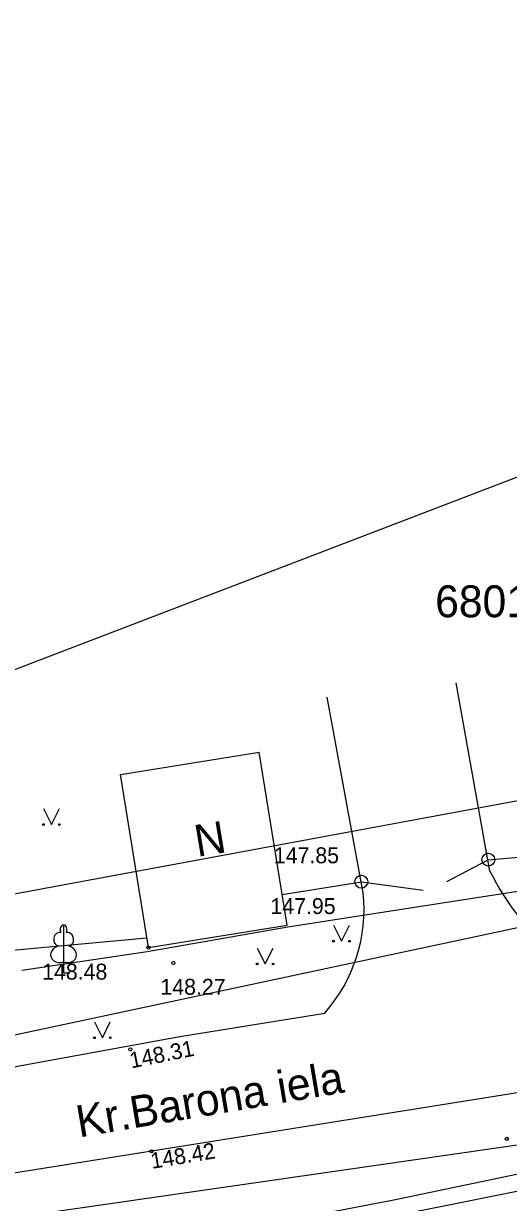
# Model space of a CAD drawing. Extents: x 728492 to 729038, y 272968 to 273171.
# Drawn here: x 728626.42 to 728641.64, y 273065.2 to 273102.17 of the extents above; entities that cross this region are included whole.
import ezdxf

# ---------------------------------------------------------------- set-up
doc = ezdxf.new("R2010")
doc.units = 0
for name, color, linetype in [('APGR_SARK_####_####_#', 7, 'Continuous'), ('BUVE_EKAS_BPAL_####_#', 7, 'Continuous'), ('BUVE_EKAS_RAKS_TKST_#', 7, 'Continuous'), ('CELI_CMAL_####_####_#', 7, 'Continuous'), ('CELI_IELA_####_TKST_#', 7, 'Continuous'), ('ELEK_VADV_ZSPR_####_#', 7, 'Continuous'), ('NORB_ELEM_####_####_#', 7, 'Continuous'), ('NORB_ZOGS_BARJ_####_#', 7, 'Continuous'), ('NORB_ZOGS_KOKA_####_#', 7, 'Continuous'), ('NORB_ZOGS_ZMET_####_#', 7, 'Continuous'), ('RAMI_UZMR_####_####_#', 7, 'Continuous'), ('RELJ_AATZ_####_TKST_#', 7, 'Continuous'), ('RELJ_ELEM_####_####_#', 7, 'Continuous'), ('ROBZ_KADS_####_TKST_#', 7, 'Continuous'), ('ROBZ_UZMR_####_####_#', 7, 'Continuous'), ('SILT_VADP_UDEN_####_#', 7, 'Continuous'), ('SKAN_VADP_PAST_####_#', 7, 'Continuous'), ('TERT_ELEM_####_####_#', 7, 'Continuous'), ('UDTK_VADP_UDEN_####_#', 7, 'Continuous')]:
    doc.layers.add(name, color=color, linetype=linetype)

msp = doc.modelspace()

# ---------------------------------------------------------------- linework, layer by layer
at = {"layer": 'APGR_SARK_####_####_#'}
msp.add_lwpolyline([(728659.143, 273080.982), (728541.407, 273059.185)], dxfattribs=at)
at = {"layer": 'BUVE_EKAS_BPAL_####_#'}
for p, q in [((728629.468, 273078.625), (728633.817, 273079.325)), ((728634.691, 273073.895), (728633.817, 273079.325)), ((728630.342, 273073.195), (728629.468, 273078.625)), ((728630.342, 273073.195), (728634.691, 273073.895))]:
    msp.add_line(p, q, dxfattribs=at)
at = {"layer": 'CELI_CMAL_####_####_#'}
for p, q in [((728631.326, 273070.412), (728635.871, 273071.143)), ((728615.604, 273067.516), (728631.326, 273070.412))]:
    msp.add_line(p, q, dxfattribs=at)
for points in [[(728641.055, 273075.594), (728639.999, 273081.495)], [(728637.077, 273074.913), (728635.953, 273081.045)]]:
    msp.add_lwpolyline(points, dxfattribs=at)
for centre, radius, start, end in [((728648.689, 273079.412), 8.535, 206.5697, 229.9071), ((728632.23, 273074.386), 4.875, 318.3108, 6.2049)]:
    msp.add_arc(centre, radius, start, end, dxfattribs=at)
at = {"layer": 'ELEK_VADV_ZSPR_####_#'}
msp.add_line((728617.923, 273068.708), (728666.081, 273078.979), dxfattribs=at)
at = {"layer": 'NORB_ELEM_####_####_#'}
for centre in [(728641.005, 273075.952), (728637.021, 273075.261)]:
    msp.add_circle(centre, 0.202, dxfattribs=at)
at = {"layer": 'NORB_ZOGS_BARJ_####_#'}
for points in [[(728639.703, 273075.267), (728641.005, 273075.952)], [(728637.021, 273075.261), (728638.957, 273074.994)]]:
    msp.add_lwpolyline(points, dxfattribs=at)
at = {"layer": 'NORB_ZOGS_KOKA_####_#'}
msp.add_lwpolyline([(728626.077, 273073.117), (728630.292, 273073.503)], dxfattribs=at)
at = {"layer": 'NORB_ZOGS_ZMET_####_#'}
for points in [[(728641.005, 273075.952), (728642.549, 273076.089), (728643.396, 273076.357)], [(728634.536, 273074.861), (728637.021, 273075.261)]]:
    msp.add_lwpolyline(points, dxfattribs=at)
at = {"layer": 'RAMI_UZMR_####_####_#'}
msp.add_lwpolyline([(728726.814, 273102.175), (728686.914, 273096.216), (728659.323, 273094.615), (728619.629, 273079.414), (728545.121, 273067.256)], dxfattribs=at)
at = {"layer": 'RELJ_ELEM_####_####_#'}
for centre in [(728630.342, 273073.195), (728631.123, 273072.712), (728629.774, 273070.006), (728641.586, 273067.199), (728630.433, 273066.806)]:
    msp.add_circle(centre, 0.05, dxfattribs=at)
at = {"layer": 'ROBZ_UZMR_####_####_#'}
for p, q in [((728664.052, 273078.4), (728634.713, 273073.836)), ((728634.713, 273073.836), (728630.305, 273073.064)), ((728630.305, 273073.064), (728626.365, 273072.477))]:
    msp.add_line(p, q, dxfattribs=at)
at = {"layer": 'SILT_VADP_UDEN_####_#'}
for points in [[(728554.662, 273032.952), (728554.113, 273035.473), (728554.267, 273035.774), (728581.419, 273054.878), (728582.018, 273055.208), (728610.89, 273060.328), (728630.183, 273063.782), (728638.039, 273065.289), (728652.893, 273068.386), (728653.925, 273076.859), (728654.802, 273077.089)], [(728555.193, 273032.922), (728554.64, 273035.405), (728554.656, 273035.436), (728581.684, 273054.453), (728582.187, 273054.73), (728610.978, 273059.835), (728630.274, 273063.29), (728638.144, 273064.8), (728653.493, 273067.873), (728654.384, 273076.462), (728654.897, 273076.597)]]:
    msp.add_lwpolyline(points, dxfattribs=at)
at = {"layer": 'SKAN_VADP_PAST_####_#'}
msp.add_lwpolyline([(728616.534, 273064.605), (728669.124, 273072.987)], dxfattribs=at)
at = {"layer": 'TERT_ELEM_####_####_#'}
for p, q in [((728627.047, 273077.555), (728627.297, 273077.055)), ((728627.297, 273077.055), (728627.547, 273077.555)), ((728636.151, 273073.898), (728636.401, 273073.398)), ((728636.401, 273073.398), (728636.651, 273073.898)), ((728633.754, 273073.183), (728634.004, 273072.683)), ((728634.004, 273072.683), (728634.254, 273073.183)), ((728627.679, 273072.75), (728627.679, 273072.403)), ((728627.679, 273072.403), (728627.879, 273072.403)), ((728628.645, 273070.869), (728628.895, 273070.369)), ((728628.895, 273070.369), (728629.145, 273070.869))]:
    msp.add_line(p, q, dxfattribs=at)
for points in [[(728627.679, 273073.903), (728627.679, 273072.75)], [(728627.769, 273073.671), (728627.768, 273073.672)]]:
    msp.add_lwpolyline(points, dxfattribs=at)
for centre, radius in [((728627.046, 273077.054), 0.028), ((728627.546, 273077.054), 0.0263), ((728636.151, 273073.397), 0.028), ((728636.651, 273073.397), 0.0263), ((728633.753, 273072.683), 0.028), ((728634.253, 273072.683), 0.0263), ((728628.645, 273070.369), 0.028), ((728629.145, 273070.369), 0.0263)]:
    msp.add_circle(centre, radius, dxfattribs=at)
for centre, major_axis, ratio, start_param, end_param in [((728627.551, 273073.458), (-0.039, -0.212), 0.861323, 3.141593, 6.283185), ((728627.679, 273073.753), (0, -0.15), 0.707107, 3.14537, 5.287485), ((728627.679, 273073.753), (0, -0.15), 0.707107, 0.995701, 3.137816), ((728627.807, 273073.458), (0.039, -0.212), 0.861323, 0, 3.141593), ((728627.589, 273072.996), (0.307, 0.095), 0.814445, 1.570796, 4.752015), ((728627.769, 273072.996), (-0.307, 0.095), 0.814445, 1.531171, 4.712389)]:
    msp.add_ellipse(centre, major_axis=major_axis, ratio=ratio, start_param=start_param, end_param=end_param, dxfattribs=at)
at = {"layer": 'UDTK_VADP_UDEN_####_#'}
msp.add_lwpolyline([(728536.753, 273051.73), (728562.041, 273055.954), (728585.763, 273058.374), (728605.397, 273061.619), (728606.945, 273061.767), (728607.469, 273061.897), (728613.688, 273063.022), (728614.11, 273063.005), (728657.437, 273069.243)], dxfattribs=at)

# ---------------------------------------------------------------- texts
at = {"layer": 'BUVE_EKAS_RAKS_TKST_#'}
msp.add_text('N', height=1, rotation=9.474, dxfattribs=at).set_placement((728631.876, 273076.036))
at = {"layer": 'CELI_IELA_####_TKST_#'}
msp.add_text('Kr.Barona iela', height=1, rotation=9.638, dxfattribs=at).set_placement((728628.166, 273067.239))
at = {"layer": 'RELJ_AATZ_####_TKST_#'}
for s, p in [(' 147.85', (728634.09, 273075.84)), (' 147.95', (728633.983, 273074.248)), (' 148.48', (728626.82, 273072.191)), (' 148.27', (728630.531, 273071.716))]:
    msp.add_text(s, height=0.5, dxfattribs=at).set_placement(p)
for s, rotation, p in [('148.31', 11.4304, (728629.805, 273069.405)), ('148.42', 9.47, (728630.452, 273066.256))]:
    msp.add_text(s, height=0.5, rotation=rotation, dxfattribs=at).set_placement(p)
at = {"layer": 'ROBZ_KADS_####_TKST_#'}
msp.add_text('68010040266', height=1, dxfattribs=at).set_placement((728639.338, 273083.556))

doc.saveas('drawing.dxf')
